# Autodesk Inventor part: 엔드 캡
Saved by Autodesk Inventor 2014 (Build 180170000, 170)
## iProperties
Created: 2026-04
Part Number: 엔드 캡
Material: 일반
Document SubType Name: Modeling
Designer: dg
Density: 1 g/cm^3
Appearance: 기본값
Author: dg
Author: jhkim
Creation Date: 2026-03-26
Sending System: Autodesk Inventor 2026
Preprocessor: ST-DEVELOPER v20.1
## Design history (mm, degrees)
node "엔드 캡1"
node "솔리드1"
node "기준1"
